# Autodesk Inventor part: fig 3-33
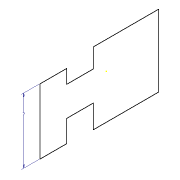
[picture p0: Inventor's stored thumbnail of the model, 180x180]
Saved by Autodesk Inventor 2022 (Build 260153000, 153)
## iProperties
Created: 2018-03
Part Number: fig 3-33
Material: Generic
Document SubType Name: Modeling
Designer: CADCIM 00
Density: 1 g/cm^3
Appearance: Default
Author: CADCIM 00
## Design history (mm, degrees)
sketch "Sketch1"
  geometry: L1 (-4.566, 7.164)-(2.434, 7.164); L2 (2.434, 7.164)-(2.434, 4.293); L3 (2.434, 4.293)-(0.957, 4.293); L4 (0.957, 4.293)-(0.957, 1.422); L5 (0.957, 1.422)-(3.008, 1.422); L6 (3.008, 1.422)-(3.008, -5.605); L7 (3.008, -5.605)-(-4.703, -5.605); L8 (-4.703, -5.605)-(-4.703, 1.422); L9 (-4.703, 1.422)-(-2.215, 1.422); L10 (-2.215, 1.422)-(-2.215, 4.293); L11 (-2.215, 4.293)-(-4.566, 4.293); L12 (-4.566, 4.293)-(-4.566, 7.164); 1 further point
  constraints: 24 end point, 9 perpendicular, 4 point on line, 1 horizontal
  dimensions: "d0" = 7 distance of L1.start L1.end
